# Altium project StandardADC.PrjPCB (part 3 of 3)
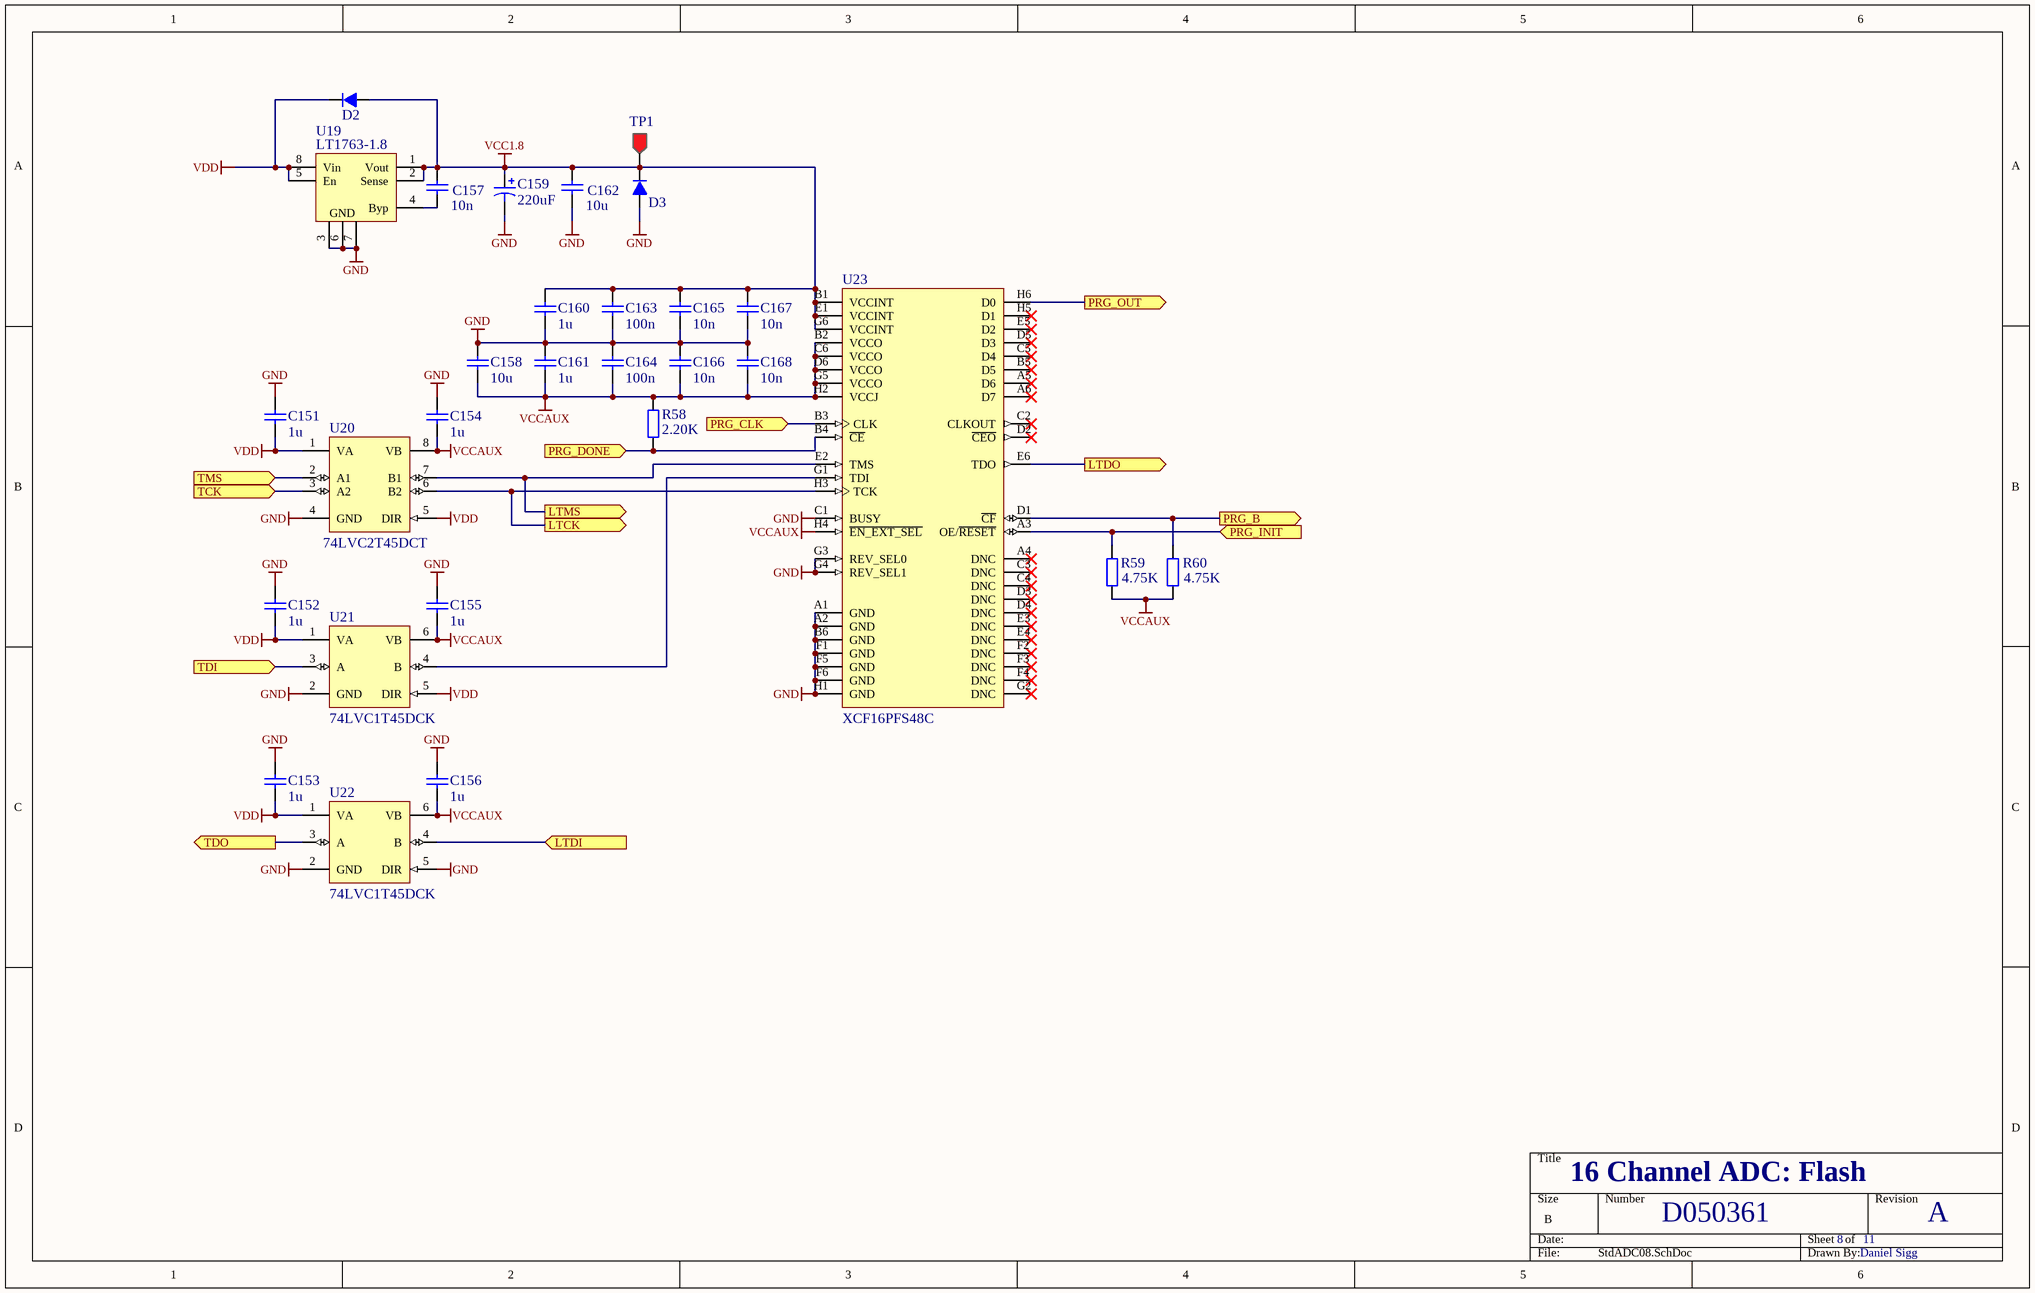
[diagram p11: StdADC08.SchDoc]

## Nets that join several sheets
+5V: FPGA1/ADC1 (C96A.1 C111A.1 U8A.12 U12A.12), FPGA1/ADC1 (7 pins), FPGA1/ADC2 (C96B.1 C111B.1 U8B.12 U12B.12), FPGA1/ADC2 (7 pins), FPGA1/ADC3 (C96C.1 C111C.1 U8C.12 U12C.12), FPGA1/ADC3 (7 pins), FPGA1/ADC4 (C96D.1 C111D.1 U8D.12 U12D.12), FPGA1/ADC4 (7 pins), FPGA1/ADC5 (C96E.1 C111E.1 U8E.12 U12E.12), FPGA1/ADC5 (7 pins), FPGA1/ADC6 (C96F.1 C111F.1 U8F.12 U12F.12), FPGA1/ADC6 (7 pins), FPGA1/ADC7 (C96G.1 C111G.1 U8G.12 U12G.12), FPGA1/ADC7 (7 pins), FPGA1/ADC8 (C96H.1 C111H.1 U8H.12 U12H.12), FPGA1/ADC8 (7 pins), FPGA1/DAC (5 pins), FPGA2/ADC1 (C96I.1 C111I.1 U8I.12 U12I.12), FPGA2/ADC1 (7 pins), FPGA2/ADC2 (C96J.1 C111J.1 U8J.12 U12J.12), FPGA2/ADC2 (7 pins), FPGA2/ADC3 (C96K.1 C111K.1 U8K.12 U12K.12), FPGA2/ADC3 (7 pins), FPGA2/ADC4 (C96L.1 C111L.1 U8L.12 U12L.12), FPGA2/ADC4 (7 pins), FPGA2/ADC5 (C96M.1 C111M.1 U8M.12 U12M.12), FPGA2/ADC5 (7 pins), FPGA2/ADC6 (C96N.1 C111N.1 U8N.12 U12N.12), FPGA2/ADC6 (7 pins), FPGA2/ADC7 (C96O.1 C111O.1 U8O.12 U12O.12), FPGA2/ADC7 (7 pins), FPGA2/ADC8 (C96P.1 C111P.1 U8P.12 U12P.12), FPGA2/ADC8 (7 pins), FPGA2/DAC (5 pins), StdADC10 (13 pins)
+15V: FPGA1 (C6A.2 U3A.2), FPGA1/ADC1 (12 pins), FPGA1/ADC1 (8 pins), FPGA1/ADC2 (12 pins), FPGA1/ADC2 (8 pins), FPGA1/ADC3 (12 pins), FPGA1/ADC3 (8 pins), FPGA1/ADC4 (12 pins), FPGA1/ADC4 (8 pins), FPGA1/ADC5 (12 pins), FPGA1/ADC5 (8 pins), FPGA1/ADC6 (12 pins), FPGA1/ADC6 (8 pins), FPGA1/ADC7 (12 pins), FPGA1/ADC7 (8 pins), FPGA1/ADC8 (12 pins), FPGA1/ADC8 (8 pins), FPGA1/DAC (6 pins), FPGA2 (C6B.2 U3B.2), FPGA2/ADC1 (12 pins), FPGA2/ADC1 (8 pins), FPGA2/ADC2 (12 pins), FPGA2/ADC2 (8 pins), FPGA2/ADC3 (12 pins), FPGA2/ADC3 (8 pins), FPGA2/ADC4 (12 pins), FPGA2/ADC4 (8 pins), FPGA2/ADC5 (12 pins), FPGA2/ADC5 (8 pins), FPGA2/ADC6 (12 pins), FPGA2/ADC6 (8 pins), FPGA2/ADC7 (12 pins), FPGA2/ADC7 (8 pins), FPGA2/ADC8 (12 pins), FPGA2/ADC8 (8 pins), FPGA2/DAC (6 pins), StdADC10 (14 pins), StdADC11 (21 pins)
-5V: FPGA1/DAC (7 pins), FPGA2/DAC (7 pins), StdADC10 (13 pins)
-15V: FPGA1/ADC1 (12 pins), FPGA1/ADC1 (6 pins), FPGA1/ADC2 (12 pins), FPGA1/ADC2 (6 pins), FPGA1/ADC3 (12 pins), FPGA1/ADC3 (6 pins), FPGA1/ADC4 (12 pins), FPGA1/ADC4 (6 pins), FPGA1/ADC5 (12 pins), FPGA1/ADC5 (6 pins), FPGA1/ADC6 (12 pins), FPGA1/ADC6 (6 pins), FPGA1/ADC7 (12 pins), FPGA1/ADC7 (6 pins), FPGA1/ADC8 (12 pins), FPGA1/ADC8 (6 pins), FPGA1/DAC (6 pins), FPGA2/ADC1 (12 pins), FPGA2/ADC1 (6 pins), FPGA2/ADC2 (12 pins), FPGA2/ADC2 (6 pins), FPGA2/ADC3 (12 pins), FPGA2/ADC3 (6 pins), FPGA2/ADC4 (12 pins), FPGA2/ADC4 (6 pins), FPGA2/ADC5 (12 pins), FPGA2/ADC5 (6 pins), FPGA2/ADC6 (12 pins), FPGA2/ADC6 (6 pins), FPGA2/ADC7 (12 pins), FPGA2/ADC7 (6 pins), FPGA2/ADC8 (12 pins), FPGA2/ADC8 (6 pins), FPGA2/DAC (6 pins), StdADC10 (14 pins), StdADC11 (21 pins)
AGND: StdADC01 (16 pins), FPGA1 (C5A.1 C6A.1 U3A.4), FPGA1/ADC1 (25 pins), FPGA1/ADC1 (33 pins), FPGA1/ADC2 (25 pins), FPGA1/ADC2 (33 pins), FPGA1/ADC3 (25 pins), FPGA1/ADC3 (33 pins), FPGA1/ADC4 (25 pins), FPGA1/ADC4 (33 pins), FPGA1/ADC5 (25 pins), FPGA1/ADC5 (33 pins), FPGA1/ADC6 (25 pins), FPGA1/ADC6 (33 pins), FPGA1/ADC7 (25 pins), FPGA1/ADC7 (33 pins), FPGA1/ADC8 (25 pins), FPGA1/ADC8 (33 pins), FPGA1/DAC (22 pins), FPGA2 (C5B.1 C6B.1 U3B.4), FPGA2/ADC1 (25 pins), FPGA2/ADC1 (33 pins), FPGA2/ADC2 (25 pins), FPGA2/ADC2 (33 pins), FPGA2/ADC3 (25 pins), FPGA2/ADC3 (33 pins), FPGA2/ADC4 (25 pins), FPGA2/ADC4 (33 pins), FPGA2/ADC5 (25 pins), FPGA2/ADC5 (33 pins), FPGA2/ADC6 (25 pins), FPGA2/ADC6 (33 pins), FPGA2/ADC7 (25 pins), FPGA2/ADC7 (33 pins), FPGA2/ADC8 (25 pins), FPGA2/ADC8 (33 pins), FPGA2/DAC (22 pins), StdADC10 (39 pins), StdADC11 (32 pins)
GND: StdADC01 (60 pins), FPGA1/ADC1 (K1A.5), FPGA1/ADC1 (17 pins), FPGA1/ADC2 (K1B.5), FPGA1/ADC2 (17 pins), FPGA1/ADC3 (K1C.5), FPGA1/ADC3 (17 pins), FPGA1/ADC4 (K1D.5), FPGA1/ADC4 (17 pins), FPGA1/ADC5 (K1E.5), FPGA1/ADC5 (17 pins), FPGA1/ADC6 (K1F.5), FPGA1/ADC6 (17 pins), FPGA1/ADC7 (K1G.5), FPGA1/ADC7 (17 pins), FPGA1/ADC8 (K1H.5), FPGA1/ADC8 (17 pins), FPGA1/DAC (9 pins), FPGA1 (R3A.1), FPGA1 (R6A.2), FPGA1 (142 pins), FPGA2/ADC1 (K1I.5), FPGA2/ADC1 (17 pins), FPGA2/ADC2 (K1J.5), FPGA2/ADC2 (17 pins), FPGA2/ADC3 (K1K.5), FPGA2/ADC3 (17 pins), FPGA2/ADC4 (K1L.5), FPGA2/ADC4 (17 pins), FPGA2/ADC5 (K1M.5), FPGA2/ADC5 (17 pins), FPGA2/ADC6 (K1N.5), FPGA2/ADC6 (17 pins), FPGA2/ADC7 (K1O.5), FPGA2/ADC7 (17 pins), FPGA2/ADC8 (K1P.5), FPGA2/ADC8 (17 pins), FPGA2/DAC (9 pins), FPGA2 (R3B.1), FPGA2 (R6B.2), FPGA2 (142 pins), StdADC10 (12 pins), StdADC11 (31 pins), StdADC08 (35 pins)
N5V: StdADC01 (P2.41 P2.43 P2.45 P2.47), StdADC10 (R95.1)
N15V: StdADC01 (P2.57 P2.59 P2.61 P2.63), StdADC11 (R126.1)
P5V: StdADC01 (P2.33 P2.35 P2.37 P2.39), StdADC10 (R76.1)
P15V: StdADC01 (P2.49 P2.51 P2.53 P2.55), StdADC11 (R125.1)
VCC: FPGA1/ADC1 (6 pins), FPGA1/ADC2 (6 pins), FPGA1/ADC3 (6 pins), FPGA1/ADC4 (6 pins), FPGA1/ADC5 (6 pins), FPGA1/ADC6 (6 pins), FPGA1/ADC7 (6 pins), FPGA1/ADC8 (6 pins), FPGA1/DAC (5 pins), FPGA1 (L3A.2 L4A.2), FPGA2/ADC1 (6 pins), FPGA2/ADC2 (6 pins), FPGA2/ADC3 (6 pins), FPGA2/ADC4 (6 pins), FPGA2/ADC5 (6 pins), FPGA2/ADC6 (6 pins), FPGA2/ADC7 (6 pins), FPGA2/ADC8 (6 pins), FPGA2/DAC (5 pins), FPGA2 (L3B.2 L4B.2), StdADC10 (C205.1 C209.1 R77.4 TP2.1), StdADC11 (5 pins)
VCCAUX: FPGA1 (R4A.2), FPGA1 (R5A.1), FPGA1 (45 pins), FPGA2 (R4B.2), FPGA2 (R5B.1), FPGA2 (45 pins), StdADC10 (R96.4 TP6.1), StdADC08 (20 pins)
VCCIN: StdADC01 (P2.3 P2.5 P2.7 P2.9), StdADC10 (R77.1)
VCCINT: FPGA1 (28 pins), FPGA2 (28 pins), StdADC10 (R97.4 TP7.1)
VCCS: StdADC01 (P2.1), StdADC11 (9 pins)
VDD: StdADC01 (10 pins), FPGA1/ADC1 (5 pins), FPGA1/ADC2 (5 pins), FPGA1/ADC3 (5 pins), FPGA1/ADC4 (5 pins), FPGA1/ADC5 (5 pins), FPGA1/ADC6 (5 pins), FPGA1/ADC7 (5 pins), FPGA1/ADC8 (5 pins), FPGA1 (80 pins), FPGA2/ADC1 (5 pins), FPGA2/ADC2 (5 pins), FPGA2/ADC3 (5 pins), FPGA2/ADC4 (5 pins), FPGA2/ADC5 (5 pins), FPGA2/ADC6 (5 pins), FPGA2/ADC7 (5 pins), FPGA2/ADC8 (5 pins), FPGA2 (80 pins), StdADC10 (7 pins), StdADC11 (C278.2 C279.2 U53.8), StdADC08 (11 pins)
VDDIN: StdADC01 (6 pins), StdADC10 (R78.1)
VEE: FPGA1/DAC (5 pins), FPGA2/DAC (5 pins), StdADC10 (C206.1 C208.2 R79.4 TP4.1)
VEEIN: StdADC01 (P2.23 P2.25 P2.27), StdADC10 (R79.1)
ADCIN: FPGA1/ADC1 (R38A.1 R39A.1 U13A.6), FPGA1/ADC1 (R40A.2)
ADCIN: FPGA1/ADC2 (R38B.1 R39B.1 U13B.6), FPGA1/ADC2 (R40B.2)
ADCIN: FPGA1/ADC3 (R38C.1 R39C.1 U13C.6), FPGA1/ADC3 (R40C.2)
ADCIN: FPGA1/ADC4 (R38D.1 R39D.1 U13D.6), FPGA1/ADC4 (R40D.2)
ADCIN: FPGA1/ADC5 (R38E.1 R39E.1 U13E.6), FPGA1/ADC5 (R40E.2)
ADCIN: FPGA1/ADC6 (R38F.1 R39F.1 U13F.6), FPGA1/ADC6 (R40F.2)
ADCIN: FPGA1/ADC7 (R38G.1 R39G.1 U13G.6), FPGA1/ADC7 (R40G.2)
ADCIN: FPGA1/ADC8 (R38H.1 R39H.1 U13H.6), FPGA1/ADC8 (R40H.2)
ADCIN: FPGA2/ADC1 (R38I.1 R39I.1 U13I.6), FPGA2/ADC1 (R40I.2)
ADCIN: FPGA2/ADC2 (R38J.1 R39J.1 U13J.6), FPGA2/ADC2 (R40J.2)
ADCIN: FPGA2/ADC3 (R38K.1 R39K.1 U13K.6), FPGA2/ADC3 (R40K.2)
ADCIN: FPGA2/ADC4 (R38L.1 R39L.1 U13L.6), FPGA2/ADC4 (R40L.2)
ADCIN: FPGA2/ADC5 (R38M.1 R39M.1 U13M.6), FPGA2/ADC5 (R40M.2)
ADCIN: FPGA2/ADC6 (R38N.1 R39N.1 U13N.6), FPGA2/ADC6 (R40N.2)
ADCIN: FPGA2/ADC7 (R38O.1 R39O.1 U13O.6), FPGA2/ADC7 (R40O.2)
ADCIN: FPGA2/ADC8 (R38P.1 R39P.1 U13P.6), FPGA2/ADC8 (R40P.2)
BUSY1: FPGA1/ADC1 (U18A.29), FPGA1 (U4A#2.L2)
BUSY1: FPGA2/ADC1 (U18I.29), FPGA2 (U4B#2.L2)
BUSY2: FPGA1/ADC2 (U18B.29), FPGA1 (U4A#2.G3)
BUSY2: FPGA2/ADC2 (U18J.29), FPGA2 (U4B#2.G3)
BUSY3: FPGA1/ADC3 (U18C.29), FPGA1 (U4A#1.A3)
BUSY3: FPGA2/ADC3 (U18K.29), FPGA2 (U4B#1.A3)
BUSY4: FPGA1/ADC4 (U18D.29), FPGA1 (U4A#1.E8)
BUSY4: FPGA2/ADC4 (U18L.29), FPGA2 (U4B#1.E8)
BUSY5: FPGA1/ADC5 (U18E.29), FPGA1 (U4A#2.A12)
BUSY5: FPGA2/ADC5 (U18M.29), FPGA2 (U4B#2.A12)
BUSY6: FPGA1/ADC6 (U18F.29), FPGA1 (U4A#2.E15)
BUSY6: FPGA2/ADC6 (U18N.29), FPGA2 (U4B#2.E15)
BUSY7: FPGA1/ADC7 (U18G.29), FPGA1 (U4A#1.C20)
BUSY7: FPGA2/ADC7 (U18O.29), FPGA2 (U4B#1.C20)
BUSY8: FPGA1/ADC8 (U18H.29), FPGA1 (U4A#1.H18)
BUSY8: FPGA2/ADC8 (U18P.29), FPGA2 (U4B#1.H18)
CONV1: FPGA1/ADC1 (U18A.35), FPGA1 (U4A#2.H1)
CONV1: FPGA2/ADC1 (U18I.35), FPGA2 (U4B#2.H1)
CONV2: FPGA1/ADC2 (U18B.35), FPGA1 (U4A#2.C2)
CONV2: FPGA2/ADC2 (U18J.35), FPGA2 (U4B#2.C2)
CONV3: FPGA1/ADC3 (U18C.35), FPGA1 (U4A#1.D8)
CONV3: FPGA2/ADC3 (U18K.35), FPGA2 (U4B#1.D8)
CONV4: FPGA1/ADC4 (U18D.35), FPGA1 (U4A#1.A11)
CONV4: FPGA2/ADC4 (U18L.35), FPGA2 (U4B#1.A11)
CONV5: FPGA1/ADC5 (U18E.35), FPGA1 (U4A#2.D15)
CONV5: FPGA2/ADC5 (U18M.35), FPGA2 (U4B#2.D15)
CONV6: FPGA1/ADC6 (U18F.35), FPGA1 (U4A#2.B20)
CONV6: FPGA2/ADC6 (U18N.35), FPGA2 (U4B#2.B20)
CONV7: FPGA1/ADC7 (U18G.35), FPGA1 (U4A#1.H19)
CONV7: FPGA2/ADC7 (U18O.35), FPGA2 (U4B#1.H19)
CONV8: FPGA1/ADC8 (U18H.35), FPGA1 (U4A#1.L22)
CONV8: FPGA2/ADC8 (U18P.35), FPGA2 (U4B#1.L22)
D001: FPGA1/ADC1 (U18A.5), FPGA1 (U4A#2.L1)
D001: FPGA2/ADC1 (U18I.5), FPGA2 (U4B#2.L1)
D002: FPGA1/ADC2 (U18B.5), FPGA1 (U4A#2.G5)
D002: FPGA2/ADC2 (U18J.5), FPGA2 (U4B#2.G5)
D003: FPGA1/ADC3 (U18C.5), FPGA1 (U4A#1.A4)
D003: FPGA2/ADC3 (U18K.5), FPGA2 (U4B#1.A4)
D004: FPGA1/ADC4 (U18D.5), FPGA1 (U4A#1.A8)
D004: FPGA2/ADC4 (U18L.5), FPGA2 (U4B#1.A8)
D005: FPGA1/ADC5 (U18E.5), FPGA1 (U4A#2.B12)
D005: FPGA2/ADC5 (U18M.5), FPGA2 (U4B#2.B12)
D006: FPGA1/ADC6 (U18F.5), FPGA1 (U4A#2.A16)
D006: FPGA2/ADC6 (U18N.5), FPGA2 (U4B#2.A16)
D007: FPGA1/ADC7 (U18G.5), FPGA1 (U4A#1.C21)
D007: FPGA2/ADC7 (U18O.5), FPGA2 (U4B#1.C21)
D008: FPGA1/ADC8 (U18H.5), FPGA1 (U4A#1.J17)
D008: FPGA2/ADC8 (U18P.5), FPGA2 (U4B#1.J17)
D011: FPGA1/ADC1 (U18A.8), FPGA1 (U4A#2.L4)
D011: FPGA2/ADC1 (U18I.8), FPGA2 (U4B#2.L4)
D012: FPGA1/ADC2 (U18B.8), FPGA1 (U4A#2.H5)
D012: FPGA2/ADC2 (U18J.8), FPGA2 (U4B#2.H5)
D013: FPGA1/ADC3 (U18C.8), FPGA1 (U4A#1.B4)
D013: FPGA2/ADC3 (U18K.8), FPGA2 (U4B#1.B4)
D014: FPGA1/ADC4 (U18D.8), FPGA1 (U4A#1.B8)
D014: FPGA2/ADC4 (U18L.8), FPGA2 (U4B#1.B8)
D015: FPGA1/ADC5 (U18E.8), FPGA1 (U4A#2.C12)
D015: FPGA2/ADC5 (U18M.8), FPGA2 (U4B#2.C12)
D016: FPGA1/ADC6 (U18F.8), FPGA1 (U4A#2.B16)
D016: FPGA2/ADC6 (U18N.8), FPGA2 (U4B#2.B16)
D017: FPGA1/ADC7 (U18G.8), FPGA1 (U4A#1.C22)
D017: FPGA2/ADC7 (U18O.8), FPGA2 (U4B#1.C22)
D018: FPGA1/ADC8 (U18H.8), FPGA1 (U4A#1.H21)
D018: FPGA2/ADC8 (U18P.8), FPGA2 (U4B#1.H21)
D021: FPGA1/ADC1 (U18A.9), FPGA1 (U4A#2.L3)
D021: FPGA2/ADC1 (U18I.9), FPGA2 (U4B#2.L3)
D022: FPGA1/ADC2 (U18B.9), FPGA1 (U4A#2.F3)
D022: FPGA2/ADC2 (U18J.9), FPGA2 (U4B#2.F3)
D023: FPGA1/ADC3 (U18C.9), FPGA1 (U4A#1.C5)
D023: FPGA2/ADC3 (U18K.9), FPGA2 (U4B#1.C5)
D024: FPGA1/ADC4 (U18D.9), FPGA1 (U4A#1.E9)
D024: FPGA2/ADC4 (U18L.9), FPGA2 (U4B#1.E9)
D025: FPGA1/ADC5 (U18E.9), FPGA1 (U4A#2.D12)
D025: FPGA2/ADC5 (U18M.9), FPGA2 (U4B#2.D12)
D026: FPGA1/ADC6 (U18F.9), FPGA1 (U4A#2.C16)
D026: FPGA2/ADC6 (U18N.9), FPGA2 (U4B#2.C16)
D027: FPGA1/ADC7 (U18G.9), FPGA1 (U4A#1.D19)
D027: FPGA2/ADC7 (U18O.9), FPGA2 (U4B#1.D19)
D028: FPGA1/ADC8 (U18H.9), FPGA1 (U4A#1.H22)
D028: FPGA2/ADC8 (U18P.9), FPGA2 (U4B#1.H22)
D031: FPGA1/ADC1 (U18A.10), FPGA1 (U4A#2.L6)
D031: FPGA2/ADC1 (U18I.10), FPGA2 (U4B#2.L6)
D032: FPGA1/ADC2 (U18B.10), FPGA1 (U4A#2.F2)
D032: FPGA2/ADC2 (U18J.10), FPGA2 (U4B#2.F2)
D033: FPGA1/ADC3 (U18C.10), FPGA1 (U4A#1.D5)
D033: FPGA2/ADC3 (U18K.10), FPGA2 (U4B#1.D5)
D034: FPGA1/ADC4 (U18D.10), FPGA1 (U4A#1.F9)
D034: FPGA2/ADC4 (U18L.10), FPGA2 (U4B#1.F9)
D035: FPGA1/ADC5 (U18E.10), FPGA1 (U4A#2.E12)
D035: FPGA2/ADC5 (U18M.10), FPGA2 (U4B#2.E12)
D036: FPGA1/ADC6 (U18F.10), FPGA1 (U4A#2.D16)
D036: FPGA2/ADC6 (U18N.10), FPGA2 (U4B#2.D16)
D037: FPGA1/ADC7 (U18G.10), FPGA1 (U4A#1.D20)
D037: FPGA2/ADC7 (U18O.10), FPGA2 (U4B#1.D20)
D038: FPGA1/ADC8 (U18H.10), FPGA1 (U4A#1.J18)
D038: FPGA2/ADC8 (U18P.10), FPGA2 (U4B#1.J18)
D041: FPGA1/ADC1 (U18A.11), FPGA1 (U4A#2.L5)
D041: FPGA2/ADC1 (U18I.11), FPGA2 (U4B#2.L5)
D042: FPGA1/ADC2 (U18B.11), FPGA1 (U4A#2.F5)
D042: FPGA2/ADC2 (U18J.11), FPGA2 (U4B#2.F5)
D043: FPGA1/ADC3 (U18C.11), FPGA1 (U4A#1.A5)
D043: FPGA2/ADC3 (U18K.11), FPGA2 (U4B#1.A5)
D044: FPGA1/ADC4 (U18D.11), FPGA1 (U4A#1.A9)
D044: FPGA2/ADC4 (U18L.11), FPGA2 (U4B#1.A9)
D045: FPGA1/ADC5 (U18E.11), FPGA1 (U4A#2.F12)
D045: FPGA2/ADC5 (U18M.11), FPGA2 (U4B#2.F12)
D046: FPGA1/ADC6 (U18F.11), FPGA1 (U4A#2.E16)
D046: FPGA2/ADC6 (U18N.11), FPGA2 (U4B#2.E16)
D047: FPGA1/ADC7 (U18G.11), FPGA1 (U4A#1.D21)
D047: FPGA2/ADC7 (U18O.11), FPGA2 (U4B#1.D21)
D048: FPGA1/ADC8 (U18H.11), FPGA1 (U4A#1.J19)
D048: FPGA2/ADC8 (U18P.11), FPGA2 (U4B#1.J19)
D051: FPGA1/ADC1 (U18A.12), FPGA1 (U4A#2.K2)
D051: FPGA2/ADC1 (U18I.12), FPGA2 (U4B#2.K2)
D052: FPGA1/ADC2 (U18B.12), FPGA1 (U4A#2.G6)
D052: FPGA2/ADC2 (U18J.12), FPGA2 (U4B#2.G6)
D053: FPGA1/ADC3 (U18C.12), FPGA1 (U4A#1.B5)
D053: FPGA2/ADC3 (U18K.12), FPGA2 (U4B#1.B5)
D054: FPGA1/ADC4 (U18D.12), FPGA1 (U4A#1.B9)
D054: FPGA2/ADC4 (U18L.12), FPGA2 (U4B#1.B9)
D055: FPGA1/ADC5 (U18E.12), FPGA1 (U4A#2.A13)
D055: FPGA2/ADC5 (U18M.12), FPGA2 (U4B#2.A13)
D056: FPGA1/ADC6 (U18F.12), FPGA1 (U4A#2.F16)
D056: FPGA2/ADC6 (U18N.12), FPGA2 (U4B#2.F16)
D057: FPGA1/ADC7 (U18G.12), FPGA1 (U4A#1.D22)
D057: FPGA2/ADC7 (U18O.12), FPGA2 (U4B#1.D22)
D058: FPGA1/ADC8 (U18H.12), FPGA1 (U4A#1.J21)
D058: FPGA2/ADC8 (U18P.12), FPGA2 (U4B#1.J21)
D061: FPGA1/ADC1 (U18A.13), FPGA1 (U4A#2.K1)
D061: FPGA2/ADC1 (U18I.13), FPGA2 (U4B#2.K1)
D062: FPGA1/ADC2 (U18B.13), FPGA1 (U4A#2.E2)
D062: FPGA2/ADC2 (U18J.13), FPGA2 (U4B#2.E2)
D063: FPGA1/ADC3 (U18C.13), FPGA1 (U4A#1.E5)
D063: FPGA2/ADC3 (U18K.13), FPGA2 (U4B#1.E5)
D064: FPGA1/ADC4 (U18D.13), FPGA1 (U4A#1.D9)
D064: FPGA2/ADC4 (U18L.13), FPGA2 (U4B#1.D9)
D065: FPGA1/ADC5 (U18E.13), FPGA1 (U4A#2.B13)
D065: FPGA2/ADC5 (U18M.13), FPGA2 (U4B#2.B13)
D066: FPGA1/ADC6 (U18F.13), FPGA1 (U4A#2.B17)
D066: FPGA2/ADC6 (U18N.13), FPGA2 (U4B#2.B17)
D067: FPGA1/ADC7 (U18G.13), FPGA1 (U4A#1.F18)
D067: FPGA2/ADC7 (U18O.13), FPGA2 (U4B#1.F18)
D068: FPGA1/ADC8 (U18H.13), FPGA1 (U4A#1.J22)
D068: FPGA2/ADC8 (U18P.13), FPGA2 (U4B#1.J22)
D071: FPGA1/ADC1 (U18A.14), FPGA1 (U4A#2.K4)
D071: FPGA2/ADC1 (U18I.14), FPGA2 (U4B#2.K4)
D072: FPGA1/ADC2 (U18B.14), FPGA1 (U4A#2.E1)
D072: FPGA2/ADC2 (U18J.14), FPGA2 (U4B#2.E1)
D073: FPGA1/ADC3 (U18C.14), FPGA1 (U4A#1.D6)
D073: FPGA2/ADC3 (U18K.14), FPGA2 (U4B#1.D6)
D074: FPGA1/ADC4 (U18D.14), FPGA1 (U4A#1.A10)
D074: FPGA2/ADC4 (U18L.14), FPGA2 (U4B#1.A10)
D075: FPGA1/ADC5 (U18E.14), FPGA1 (U4A#2.C13)
D075: FPGA2/ADC5 (U18M.14), FPGA2 (U4B#2.C13)
D076: FPGA1/ADC6 (U18F.14), FPGA1 (U4A#2.C17)
D076: FPGA2/ADC6 (U18N.14), FPGA2 (U4B#2.C17)
D077: FPGA1/ADC7 (U18G.14), FPGA1 (U4A#1.E18)
D077: FPGA2/ADC7 (U18O.14), FPGA2 (U4B#1.E18)
D078: FPGA1/ADC8 (U18H.14), FPGA1 (U4A#1.K17)
D078: FPGA2/ADC8 (U18P.14), FPGA2 (U4B#1.K17)
D081: FPGA1/ADC1 (U18A.15), FPGA1 (U4A#2.K3)
D081: FPGA2/ADC1 (U18I.15), FPGA2 (U4B#2.K3)
D082: FPGA1/ADC2 (U18B.15), FPGA1 (U4A#2.F4)
D082: FPGA2/ADC2 (U18J.15), FPGA2 (U4B#2.F4)
D083: FPGA1/ADC3 (U18C.15), FPGA1 (U4A#1.E6)
D083: FPGA2/ADC3 (U18K.15), FPGA2 (U4B#1.E6)
D084: FPGA1/ADC4 (U18D.15), FPGA1 (U4A#1.E10)
D084: FPGA2/ADC4 (U18L.15), FPGA2 (U4B#1.E10)
D085: FPGA1/ADC5 (U18E.15), FPGA1 (U4A#2.D13)
D085: FPGA2/ADC5 (U18M.15), FPGA2 (U4B#2.D13)
D086: FPGA1/ADC6 (U18F.15), FPGA1 (U4A#2.D17)
D086: FPGA2/ADC6 (U18N.15), FPGA2 (U4B#2.D17)
D087: FPGA1/ADC7 (U18G.15), FPGA1 (U4A#1.E19)
D087: FPGA2/ADC7 (U18O.15), FPGA2 (U4B#1.E19)
D088: FPGA1/ADC8 (U18H.15), FPGA1 (U4A#1.K18)
D088: FPGA2/ADC8 (U18P.15), FPGA2 (U4B#1.K18)
D091: FPGA1/ADC1 (U18A.16), FPGA1 (U4A#2.K6)
D091: FPGA2/ADC1 (U18I.16), FPGA2 (U4B#2.K6)
D092: FPGA1/ADC2 (U18B.16), FPGA1 (U4A#2.E3)
D092: FPGA2/ADC2 (U18J.16), FPGA2 (U4B#2.E3)
D093: FPGA1/ADC3 (U18C.16), FPGA1 (U4A#1.B6)
D093: FPGA2/ADC3 (U18K.16), FPGA2 (U4B#1.B6)
D094: FPGA1/ADC4 (U18D.16), FPGA1 (U4A#1.F10)
D094: FPGA2/ADC4 (U18L.16), FPGA2 (U4B#1.F10)
D095: FPGA1/ADC5 (U18E.16), FPGA1 (U4A#2.E13)
D095: FPGA2/ADC5 (U18M.16), FPGA2 (U4B#2.E13)
D096: FPGA1/ADC6 (U18F.16), FPGA1 (U4A#2.E17)
D096: FPGA2/ADC6 (U18N.16), FPGA2 (U4B#2.E17)
D097: FPGA1/ADC7 (U18G.16), FPGA1 (U4A#1.E20)
D097: FPGA2/ADC7 (U18O.16), FPGA2 (U4B#1.E20)
D098: FPGA1/ADC8 (U18H.16), FPGA1 (U4A#1.K19)
D098: FPGA2/ADC8 (U18P.16), FPGA2 (U4B#1.K19)
D101: FPGA1/ADC1 (U18A.21), FPGA1 (U4A#2.K5)
D101: FPGA2/ADC1 (U18I.21), FPGA2 (U4B#2.K5)
D102: FPGA1/ADC2 (U18B.21), FPGA1 (U4A#2.D3)
D102: FPGA2/ADC2 (U18J.21), FPGA2 (U4B#2.D3)
D103: FPGA1/ADC3 (U18C.21), FPGA1 (U4A#1.C6)
D103: FPGA2/ADC3 (U18K.21), FPGA2 (U4B#1.C6)
D104: FPGA1/ADC4 (U18D.21), FPGA1 (U4A#1.B10)
D104: FPGA2/ADC4 (U18L.21), FPGA2 (U4B#1.B10)
D105: FPGA1/ADC5 (U18E.21), FPGA1 (U4A#2.F13)
D105: FPGA2/ADC5 (U18M.21), FPGA2 (U4B#2.F13)
D106: FPGA1/ADC6 (U18F.21), FPGA1 (U4A#2.F17)
D106: FPGA2/ADC6 (U18N.21), FPGA2 (U4B#2.F17)
D107: FPGA1/ADC7 (U18G.21), FPGA1 (U4A#1.E21)
D107: FPGA2/ADC7 (U18O.21), FPGA2 (U4B#1.E21)
D108: FPGA1/ADC8 (U18H.21), FPGA1 (U4A#1.K20)
D108: FPGA2/ADC8 (U18P.21), FPGA2 (U4B#1.K20)
D111: FPGA1/ADC1 (U18A.22), FPGA1 (U4A#2.J2)
D111: FPGA2/ADC1 (U18I.22), FPGA2 (U4B#2.J2)
D112: FPGA1/ADC2 (U18B.22), FPGA1 (U4A#2.D2)
D112: FPGA2/ADC2 (U18J.22), FPGA2 (U4B#2.D2)
D113: FPGA1/ADC3 (U18C.22), FPGA1 (U4A#1.F6)
D113: FPGA2/ADC3 (U18K.22), FPGA2 (U4B#1.F6)
D114: FPGA1/ADC4 (U18D.22), FPGA1 (U4A#1.C10)
D114: FPGA2/ADC4 (U18L.22), FPGA2 (U4B#1.C10)
D115: FPGA1/ADC5 (U18E.22), FPGA1 (U4A#2.A14)
D115: FPGA2/ADC5 (U18M.22), FPGA2 (U4B#2.A14)
D116: FPGA1/ADC6 (U18F.22), FPGA1 (U4A#2.A18)
D116: FPGA2/ADC6 (U18N.22), FPGA2 (U4B#2.A18)
D117: FPGA1/ADC7 (U18G.22), FPGA1 (U4A#1.E22)
D117: FPGA2/ADC7 (U18O.22), FPGA2 (U4B#1.E22)
D118: FPGA1/ADC8 (U18H.22), FPGA1 (U4A#1.K21)
D118: FPGA2/ADC8 (U18P.22), FPGA2 (U4B#1.K21)
D121: FPGA1/ADC1 (U18A.23), FPGA1 (U4A#2.J1)
D121: FPGA2/ADC1 (U18I.23), FPGA2 (U4B#2.J1)
D122: FPGA1/ADC2 (U18B.23), FPGA1 (U4A#2.D4)
D122: FPGA2/ADC2 (U18J.23), FPGA2 (U4B#2.D4)
D123: FPGA1/ADC3 (U18C.23), FPGA1 (U4A#1.D7)
D123: FPGA2/ADC3 (U18K.23), FPGA2 (U4B#1.D7)
D124: FPGA1/ADC4 (U18D.23), FPGA1 (U4A#1.D10)
D124: FPGA2/ADC4 (U18L.23), FPGA2 (U4B#1.D10)
D125: FPGA1/ADC5 (U18E.23), FPGA1 (U4A#2.B14)
D125: FPGA2/ADC5 (U18M.23), FPGA2 (U4B#2.B14)
D126: FPGA1/ADC6 (U18F.23), FPGA1 (U4A#2.B18)
D126: FPGA2/ADC6 (U18N.23), FPGA2 (U4B#2.B18)
D127: FPGA1/ADC7 (U18G.23), FPGA1 (U4A#1.G17)
D127: FPGA2/ADC7 (U18O.23), FPGA2 (U4B#1.G17)
D128: FPGA1/ADC8 (U18H.23), FPGA1 (U4A#1.K22)
D128: FPGA2/ADC8 (U18P.23), FPGA2 (U4B#1.K22)
D131: FPGA1/ADC1 (U18A.24), FPGA1 (U4A#2.J6)
D131: FPGA2/ADC1 (U18I.24), FPGA2 (U4B#2.J6)
D132: FPGA1/ADC2 (U18B.24), FPGA1 (U4A#2.E4)
D132: FPGA2/ADC2 (U18J.24), FPGA2 (U4B#2.E4)
D133: FPGA1/ADC3 (U18C.24), FPGA1 (U4A#1.E7)
D133: FPGA2/ADC3 (U18K.24), FPGA2 (U4B#1.E7)
D134: FPGA1/ADC4 (U18D.24), FPGA1 (U4A#1.F11)
D134: FPGA2/ADC4 (U18L.24), FPGA2 (U4B#1.F11)
D135: FPGA1/ADC5 (U18E.24), FPGA1 (U4A#2.D14)
D135: FPGA2/ADC5 (U18M.24), FPGA2 (U4B#2.D14)
D136: FPGA1/ADC6 (U18F.24), FPGA1 (U4A#2.C18)
D136: FPGA2/ADC6 (U18N.24), FPGA2 (U4B#2.C18)
D137: FPGA1/ADC7 (U18G.24), FPGA1 (U4A#1.G18)
D137: FPGA2/ADC7 (U18O.24), FPGA2 (U4B#1.G18)
D138: FPGA1/ADC8 (U18H.24), FPGA1 (U4A#1.L17)
D138: FPGA2/ADC8 (U18P.24), FPGA2 (U4B#1.L17)
D141: FPGA1/ADC1 (U18A.25), FPGA1 (U4A#2.J5)
D141: FPGA2/ADC1 (U18I.25), FPGA2 (U4B#2.J5)
D142: FPGA1/ADC2 (U18B.25), FPGA1 (U4A#2.C1)
D142: FPGA2/ADC2 (U18J.25), FPGA2 (U4B#2.C1)
D143: FPGA1/ADC3 (U18C.25), FPGA1 (U4A#1.A7)
D143: FPGA2/ADC3 (U18K.25), FPGA2 (U4B#1.A7)
D144: FPGA1/ADC4 (U18D.25), FPGA1 (U4A#1.E11)
D144: FPGA2/ADC4 (U18L.25), FPGA2 (U4B#1.E11)
D145: FPGA1/ADC5 (U18E.25), FPGA1 (U4A#2.E14)
D145: FPGA2/ADC5 (U18M.25), FPGA2 (U4B#2.E14)
D146: FPGA1/ADC6 (U18F.25), FPGA1 (U4A#2.D18)
D146: FPGA2/ADC6 (U18N.25), FPGA2 (U4B#2.D18)
D147: FPGA1/ADC7 (U18G.25), FPGA1 (U4A#1.G19)
D147: FPGA2/ADC7 (U18O.25), FPGA2 (U4B#1.G19)
D148: FPGA1/ADC8 (U18H.25), FPGA1 (U4A#1.L18)
D148: FPGA2/ADC8 (U18P.25), FPGA2 (U4B#1.L18)
D151: FPGA1/ADC1 (U18A.26), FPGA1 (U4A#2.H4)
D151: FPGA2/ADC1 (U18I.26), FPGA2 (U4B#2.H4)
D152: FPGA1/ADC2 (U18B.26), FPGA1 (U4A#2.D1)
D152: FPGA2/ADC2 (U18J.26), FPGA2 (U4B#2.D1)
D153: FPGA1/ADC3 (U18C.26), FPGA1 (U4A#1.B7)
D153: FPGA2/ADC3 (U18K.26), FPGA2 (U4B#1.B7)
D154: FPGA1/ADC4 (U18D.26), FPGA1 (U4A#1.D11)
D154: FPGA2/ADC4 (U18L.26), FPGA2 (U4B#1.D11)
D155: FPGA1/ADC5 (U18E.26), FPGA1 (U4A#2.F14)
D155: FPGA2/ADC5 (U18M.26), FPGA2 (U4B#2.F14)
D156: FPGA1/ADC6 (U18F.26), FPGA1 (U4A#2.A19)
D156: FPGA2/ADC6 (U18N.26), FPGA2 (U4B#2.A19)
D157: FPGA1/ADC7 (U18G.26), FPGA1 (U4A#1.F19)
D157: FPGA2/ADC7 (U18O.26), FPGA2 (U4B#1.F19)
D158: FPGA1/ADC8 (U18H.26), FPGA1 (U4A#1.L19)
D158: FPGA2/ADC8 (U18P.26), FPGA2 (U4B#1.L19)
D161: FPGA1/ADC1 (U18A.27), FPGA1 (U4A#2.J4)
D161: FPGA2/ADC1 (U18I.27), FPGA2 (U4B#2.J4)
D162: FPGA1/ADC2 (U18B.27), FPGA1 (U4A#2.C4)
D162: FPGA2/ADC2 (U18J.27), FPGA2 (U4B#2.C4)
D163: FPGA1/ADC3 (U18C.27), FPGA1 (U4A#1.C7)
D163: FPGA2/ADC3 (U18K.27), FPGA2 (U4B#1.C7)
D164: FPGA1/ADC4 (U18D.27), FPGA1 (U4A#1.C11)
D164: FPGA2/ADC4 (U18L.27), FPGA2 (U4B#1.C11)
D165: FPGA1/ADC5 (U18E.27), FPGA1 (U4A#2.A15)
D165: FPGA2/ADC5 (U18M.27), FPGA2 (U4B#2.A15)
D166: FPGA1/ADC6 (U18F.27), FPGA1 (U4A#2.B19)
D166: FPGA2/ADC6 (U18N.27), FPGA2 (U4B#2.B19)
D167: FPGA1/ADC7 (U18G.27), FPGA1 (U4A#1.F20)
D167: FPGA2/ADC7 (U18O.27), FPGA2 (U4B#1.F20)
D168: FPGA1/ADC8 (U18H.27), FPGA1 (U4A#1.L20)
D168: FPGA2/ADC8 (U18P.27), FPGA2 (U4B#1.L20)
D171: FPGA1/ADC1 (U18A.28), FPGA1 (U4A#2.H2)
D171: FPGA2/ADC1 (U18I.28), FPGA2 (U4B#2.H2)
D172: FPGA1/ADC2 (U18B.28), FPGA1 (U4A#2.C3)
D172: FPGA2/ADC2 (U18J.28), FPGA2 (U4B#2.C3)
D173: FPGA1/ADC3 (U18C.28), FPGA1 (U4A#1.F7)
D173: FPGA2/ADC3 (U18K.28), FPGA2 (U4B#1.F7)
D174: FPGA1/ADC4 (U18D.28), FPGA1 (U4A#1.B11)
D174: FPGA2/ADC4 (U18L.28), FPGA2 (U4B#1.B11)
D175: FPGA1/ADC5 (U18E.28), FPGA1 (U4A#2.B15)
D175: FPGA2/ADC5 (U18M.28), FPGA2 (U4B#2.B15)
D176: FPGA1/ADC6 (U18F.28), FPGA1 (U4A#2.C19)
D176: FPGA2/ADC6 (U18N.28), FPGA2 (U4B#2.C19)
D177: FPGA1/ADC7 (U18G.28), FPGA1 (U4A#1.F21)
D177: FPGA2/ADC7 (U18O.28), FPGA2 (U4B#1.F21)
D178: FPGA1/ADC8 (U18H.28), FPGA1 (U4A#1.L21)
D178: FPGA2/ADC8 (U18P.28), FPGA2 (U4B#1.L21)
DBCLK: FPGA1/DAC (U24A.2), FPGA1 (U4A#1.T6)
DBCLK: FPGA2/DAC (U24B.2), FPGA2 (U4B#1.T6)
DDATA: FPGA1/DAC (U24A.1), FPGA1 (U4A#1.V2)
DDATA: FPGA2/DAC (U24B.1), FPGA2 (U4B#1.V2)
DITHER_FPGA1: FPGA1/ADC1 (R42A.2), FPGA1/ADC2 (R42B.2), FPGA1/ADC3 (R42C.2), FPGA1/ADC4 (R42D.2), FPGA1/ADC5 (R42E.2), FPGA1/ADC6 (R42F.2), FPGA1/ADC7 (R42G.2), FPGA1/ADC8 (R42H.2), FPGA1/DAC (C194A.1 R69A.1 U25A.6)
DITHER_FPGA2: FPGA2/ADC1 (R42I.2), FPGA2/ADC2 (R42J.2), FPGA2/ADC3 (R42K.2), FPGA2/ADC4 (R42L.2), FPGA2/ADC5 (R42M.2), FPGA2/ADC6 (R42N.2), FPGA2/ADC7 (R42O.2), FPGA2/ADC8 (R42P.2), FPGA2/DAC (C194B.1 R69B.1 U25B.6)
DITHN: FPGA1/DAC (R61A.1 R62A.2), FPGA1 (U4A#1.U13)
DITHN: FPGA2/DAC (R61B.1 R62B.2), FPGA2 (U4B#1.U13)
DITHP: FPGA1/DAC (R61A.2 R63A.2), FPGA1 (U4A#1.V13)
DITHP: FPGA2/DAC (R61B.2 R63B.2), FPGA2 (U4B#1.V13)
DWCLK: FPGA1/DAC (U24A.7), FPGA1 (U4A#1.V1)
DWCLK: FPGA2/DAC (U24B.7), FPGA2 (U4B#1.V1)
G2X1: FPGA1/ADC1 (U12A.1 U12A.16), FPGA1 (U4A#1.P5)
G2X1: FPGA2/ADC1 (U12I.1 U12I.16), FPGA2 (U4B#1.P5)
G2X2: FPGA1/ADC2 (U12B.1 U12B.16), FPGA1 (U4A#1.P4)
G2X2: FPGA2/ADC2 (U12J.1 U12J.16), FPGA2 (U4B#1.P4)
G2X3: FPGA1/ADC3 (U12C.1 U12C.16), FPGA1 (U4A#1.P2)
G2X3: FPGA2/ADC3 (U12K.1 U12K.16), FPGA2 (U4B#1.P2)
G2X4: FPGA1/ADC4 (U12D.1 U12D.16), FPGA1 (U4A#1.P1)
G2X4: FPGA2/ADC4 (U12L.1 U12L.16), FPGA2 (U4B#1.P1)
G2X5: FPGA1/ADC5 (U12E.1 U12E.16), FPGA1 (U4A#1.N6)
G2X5: FPGA2/ADC5 (U12M.1 U12M.16), FPGA2 (U4B#1.N6)
G2X6: FPGA1/ADC6 (U12F.1 U12F.16), FPGA1 (U4A#1.N5)
G2X6: FPGA2/ADC6 (U12N.1 U12N.16), FPGA2 (U4B#1.N5)
G2X7: FPGA1/ADC7 (U12G.1 U12G.16), FPGA1 (U4A#1.N4)
G2X7: FPGA2/ADC7 (U12O.1 U12O.16), FPGA2 (U4B#1.N4)
G2X8: FPGA1/ADC8 (U12H.1 U12H.16), FPGA1 (U4A#1.N3)
G2X8: FPGA2/ADC8 (U12P.1 U12P.16), FPGA2 (U4B#1.N3)
G10X1: FPGA1/ADC1 (U8A.1 U8A.8 U8A.9 U8A.16), FPGA1 (U4A#1.N2)
G10X1: FPGA2/ADC1 (U8I.1 U8I.8 U8I.9 U8I.16), FPGA2 (U4B#1.N2)
G10X2: FPGA1/ADC2 (U8B.1 U8B.8 U8B.9 U8B.16), FPGA1 (U4A#1.N1)
G10X2: FPGA2/ADC2 (U8J.1 U8J.8 U8J.9 U8J.16), FPGA2 (U4B#1.N1)
G10X3: FPGA1/ADC3 (U8C.1 U8C.8 U8C.9 U8C.16), FPGA1 (U4A#1.M6)
G10X3: FPGA2/ADC3 (U8K.1 U8K.8 U8K.9 U8K.16), FPGA2 (U4B#1.M6)
G10X4: FPGA1/ADC4 (U8D.1 U8D.8 U8D.9 U8D.16), FPGA1 (U4A#1.M5)
G10X4: FPGA2/ADC4 (U8L.1 U8L.8 U8L.9 U8L.16), FPGA2 (U4B#1.M5)
G10X5: FPGA1/ADC5 (U8E.1 U8E.8 U8E.9 U8E.16), FPGA1 (U4A#1.M4)
G10X5: FPGA2/ADC5 (U8M.1 U8M.8 U8M.9 U8M.16), FPGA2 (U4B#1.M4)
G10X6: FPGA1/ADC6 (U8F.1 U8F.8 U8F.9 U8F.16), FPGA1 (U4A#1.M3)
G10X6: FPGA2/ADC6 (U8N.1 U8N.8 U8N.9 U8N.16), FPGA2 (U4B#1.M3)
G10X7: FPGA1/ADC7 (U8G.1 U8G.8 U8G.9 U8G.16), FPGA1 (U4A#1.M2)
G10X7: FPGA2/ADC7 (U8O.1 U8O.8 U8O.9 U8O.16), FPGA2 (U4B#1.M2)
G10X8: FPGA1/ADC8 (U8H.1 U8H.8 U8H.9 U8H.16), FPGA1 (U4A#1.M1)
G10X8: FPGA2/ADC8 (U8P.1 U8P.8 U8P.9 U8P.16), FPGA2 (U4B#1.M1)
NetU1_6: StdADC01 (U1.6), FPGA2 (U4B#1.AA12)
NetU1_7: StdADC01 (U1.7), FPGA2 (U4B#1.AB12)
NetU1_9: StdADC01 (U1.9), FPGA1 (U4A#1.AA12)
NetU1_10: StdADC01 (U1.10), FPGA1 (U4A#1.AB12)
NetU2_6: StdADC01 (U2.6), FPGA2 (U4B#1.U12)
NetU2_7: StdADC01 (U2.7), FPGA2 (U4B#1.V12)
NetU2_9: StdADC01 (U2.9), FPGA1 (U4A#1.U12)
NetU2_10: StdADC01 (U2.10), FPGA1 (U4A#1.V12)
NetU4A#1_W12: FPGA1 (U4A#1.W12), FPGA2 (U4B#1.W12)
NetU4A#1_Y1: FPGA1 (U4A#1.Y1), FPGA2 (U4B#1.W4)
NetU4A#1_Y12: FPGA1 (U4A#1.Y12), FPGA2 (U4B#1.AA14)
NetU4A#3_A2: FPGA1 (U4A#3.A2), FPGA2 (U4B#3.A2)
NetU4A#3_A20: FPGA1 (U4A#3.A20), FPGA2 (U4B#3.A20)
NetU4A#3_A21: FPGA1 (U4A#3.A21), FPGA2 (U4B#3.A21)
NetU4A#3_AA22: FPGA1 (U4A#3.AA22), FPGA2 (U4B#3.AA22)
NetU4A#3_AB21: FPGA1 (U4A#3.AB21), FPGA2 (U4B#3.AB21)
NetU4A#3_B22: FPGA1 (U4A#3.B22), FPGA2 (U4B#3.B1)
RCLK: FPGA1 (U4A#1.U3), FPGA1 (U6A.6 U7A.6)
RCLK: FPGA2 (U4B#1.U3), FPGA2 (U6B.6 U7B.6)
RCS: FPGA1 (U4A#1.U2), FPGA1 (U5A.1 U6A.4 U7A.4)
RCS: FPGA2 (U4B#1.U2), FPGA2 (U5B.1 U6B.4 U7B.4)
RDIN: FPGA1 (U4A#1.U4), FPGA1 (U6A.5)
RDIN: FPGA2 (U4B#1.U4), FPGA2 (U6B.5)
RDOUT: FPGA1 (U4A#1.T4), FPGA1 (U7A.7)
RDOUT: FPGA2 (U4B#1.T4), FPGA2 (U7B.7)
REF5_FPGA1: FPGA1 (C5A.2 U3A.6), FPGA1/ADC1 (C150A.1 R55A.1 U17A.5), FPGA1/ADC2 (C150B.1 R55B.1 U17B.5), FPGA1/ADC3 (C150C.1 R55C.1 U17C.5), FPGA1/ADC4 (C150D.1 R55D.1 U17D.5), FPGA1/ADC5 (C150E.1 R55E.1 U17E.5), FPGA1/ADC6 (C150F.1 R55F.1 U17F.5), FPGA1/ADC7 (C150G.1 R55G.1 U17G.5), FPGA1/ADC8 (C150H.1 R55H.1 U17H.5)
REF5_FPGA2: FPGA2 (C5B.2 U3B.6), FPGA2/ADC1 (C150I.1 R55I.1 U17I.5), FPGA2/ADC2 (C150J.1 R55J.1 U17J.5), FPGA2/ADC3 (C150K.1 R55K.1 U17K.5), FPGA2/ADC4 (C150L.1 R55L.1 U17L.5), FPGA2/ADC5 (C150M.1 R55M.1 U17M.5), FPGA2/ADC6 (C150N.1 R55N.1 U17N.5), FPGA2/ADC7 (C150O.1 R55O.1 U17O.5), FPGA2/ADC8 (C150P.1 R55P.1 U17P.5)
RN1: FPGA1/ADC1 (K1A.7), FPGA1 (R12A.2 U6A.19)
RN1: FPGA2/ADC1 (K1I.7), FPGA2 (R12B.2 U6B.19)
RN2: FPGA1/ADC2 (K1B.7), FPGA1 (R16A.2 U6A.16)
RN2: FPGA2/ADC2 (K1J.7), FPGA2 (R16B.2 U6B.16)
RN3: FPGA1/ADC3 (K1C.7), FPGA1 (R20A.2 U6A.13)
RN3: FPGA2/ADC3 (K1K.7), FPGA2 (R20B.2 U6B.13)
RN4: FPGA1/ADC4 (K1D.7), FPGA1 (R24A.2 U6A.10)
RN4: FPGA2/ADC4 (K1L.7), FPGA2 (R24B.2 U6B.10)
RN5: FPGA1/ADC5 (K1E.7), FPGA1 (R13A.2 U7A.19)
RN5: FPGA2/ADC5 (K1M.7), FPGA2 (R13B.2 U7B.19)
RN6: FPGA1/ADC6 (K1F.7), FPGA1 (R17A.2 U7A.16)
RN6: FPGA2/ADC6 (K1N.7), FPGA2 (R17B.2 U7B.16)
RN7: FPGA1/ADC7 (K1G.7), FPGA1 (R21A.2 U7A.13)
RN7: FPGA2/ADC7 (K1O.7), FPGA2 (R21B.2 U7B.13)
RN8: FPGA1/ADC8 (K1H.7), FPGA1 (R25A.2 U7A.10)
RN8: FPGA2/ADC8 (K1P.7), FPGA2 (R25B.2 U7B.10)
RP1: FPGA1/ADC1 (K1A.8), FPGA1 (R10A.2 U6A.20)
RP1: FPGA2/ADC1 (K1I.8), FPGA2 (R10B.2 U6B.20)
RP2: FPGA1/ADC2 (K1B.8), FPGA1 (R14A.2 U6A.17)
RP2: FPGA2/ADC2 (K1J.8), FPGA2 (R14B.2 U6B.17)
RP3: FPGA1/ADC3 (K1C.8), FPGA1 (R18A.2 U6A.14)
RP3: FPGA2/ADC3 (K1K.8), FPGA2 (R18B.2 U6B.14)
RP4: FPGA1/ADC4 (K1D.8), FPGA1 (R22A.2 U6A.11)
RP4: FPGA2/ADC4 (K1L.8), FPGA2 (R22B.2 U6B.11)
RP5: FPGA1/ADC5 (K1E.8), FPGA1 (R11A.2 U7A.20)
RP5: FPGA2/ADC5 (K1M.8), FPGA2 (R11B.2 U7B.20)
RP6: FPGA1/ADC6 (K1F.8), FPGA1 (R15A.2 U7A.17)
RP6: FPGA2/ADC6 (K1N.8), FPGA2 (R15B.2 U7B.17)
RP7: FPGA1/ADC7 (K1G.8), FPGA1 (R19A.2 U7A.14)
RP7: FPGA2/ADC7 (K1O.8), FPGA2 (R19B.2 U7B.14)
RP8: FPGA1/ADC8 (K1H.8), FPGA1 (R23A.2 U7A.11)
RP8: FPGA2/ADC8 (K1P.8), FPGA2 (R23B.2 U7B.11)
SENS1: StdADC10 (R99.2), StdADC11 (U50.13)
SENS2: StdADC10 (R110.2), StdADC11 (U50.14)
SENS3: StdADC10 (R111.2), StdADC11 (U50.15)
SENS4: StdADC10 (R117.2), StdADC11 (U50.12)
SENS5: StdADC10 (R118.2), StdADC11 (U50.1)
SENS6: StdADC10 (R119.2), StdADC11 (U50.5)
SENS7: StdADC10 (R120.2), StdADC11 (U50.2)
SENSGND: StdADC10 (7 pins), StdADC11 (R160.1 U44.6 U48.6 U53.3)
STCK: StdADC01 (P1.51), FPGA1 (U4A#1.Y2), FPGA2 (U4B#1.Y2)
STDI: StdADC01 (P1.53), FPGA1 (U4A#1.W4)
STDO: StdADC01 (P1.54), FPGA2 (U4B#1.Y1)
STMS: StdADC01 (P1.52), FPGA1 (U4A#1.Y3), FPGA2 (U4B#1.Y3)
TEST_FPGA1: FPGA1/ADC1 (U12A.11), FPGA1/ADC2 (U12B.11), FPGA1/ADC3 (U12C.11), FPGA1/ADC4 (U12D.11), FPGA1/ADC5 (U12E.11), FPGA1/ADC6 (U12F.11), FPGA1/ADC7 (U12G.11), FPGA1/ADC8 (U12H.11), FPGA1/DAC (C201A.1 R73A.1 U27A.6)
TEST_FPGA2: FPGA2/ADC1 (U12I.11), FPGA2/ADC2 (U12J.11), FPGA2/ADC3 (U12K.11), FPGA2/ADC4 (U12L.11), FPGA2/ADC5 (U12M.11), FPGA2/ADC6 (U12N.11), FPGA2/ADC7 (U12O.11), FPGA2/ADC8 (U12P.11), FPGA2/DAC (C201B.1 R73B.1 U27B.6)
TESTEN: FPGA1/ADC1 (U12A.8 U12A.9), FPGA1/ADC2 (U12B.8 U12B.9), FPGA1/ADC3 (U12C.8 U12C.9), FPGA1/ADC4 (U12D.8 U12D.9), FPGA1/ADC5 (U12E.8 U12E.9), FPGA1/ADC6 (U12F.8 U12F.9), FPGA1/ADC7 (U12G.8 U12G.9), FPGA1/ADC8 (U12H.8 U12H.9), FPGA1 (U4A#1.T5)
TESTEN: FPGA2/ADC1 (U12I.8 U12I.9), FPGA2/ADC2 (U12J.8 U12J.9), FPGA2/ADC3 (U12K.8 U12K.9), FPGA2/ADC4 (U12L.8 U12L.9), FPGA2/ADC5 (U12M.8 U12M.9), FPGA2/ADC6 (U12N.8 U12N.9), FPGA2/ADC7 (U12O.8 U12O.9), FPGA2/ADC8 (U12P.8 U12P.9), FPGA2 (U4B#1.T5)
TSHDN: StdADC10 (R87.1), StdADC11 (5 pins)
WS1: FPGA1/ADC1 (K1A.4), FPGA1 (U4A#1.T3)
WS1: FPGA2/ADC1 (K1I.4), FPGA2 (U4B#1.T3)
WS2: FPGA1/ADC2 (K1B.4), FPGA1 (U4A#1.R4)
WS2: FPGA2/ADC2 (K1J.4), FPGA2 (U4B#1.R4)
WS3: FPGA1/ADC3 (K1C.4), FPGA1 (U4A#1.T2)
WS3: FPGA2/ADC3 (K1K.4), FPGA2 (U4B#1.T2)
WS4: FPGA1/ADC4 (K1D.4), FPGA1 (U4A#1.T1)
WS4: FPGA2/ADC4 (K1L.4), FPGA2 (U4B#1.T1)
WS5: FPGA1/ADC5 (K1E.4), FPGA1 (U4A#1.P6)
WS5: FPGA2/ADC5 (K1M.4), FPGA2 (U4B#1.P6)
WS6: FPGA1/ADC6 (K1F.4), FPGA1 (U4A#1.R5)
WS6: FPGA2/ADC6 (K1N.4), FPGA2 (U4B#1.R5)
WS7: FPGA1/ADC7 (K1G.4), FPGA1 (U4A#1.R2)
WS7: FPGA2/ADC7 (K1O.4), FPGA2 (U4B#1.R2)
WS8: FPGA1/ADC8 (K1H.4), FPGA1 (U4A#1.R1)
WS8: FPGA2/ADC8 (K1P.4), FPGA2 (U4B#1.R1)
